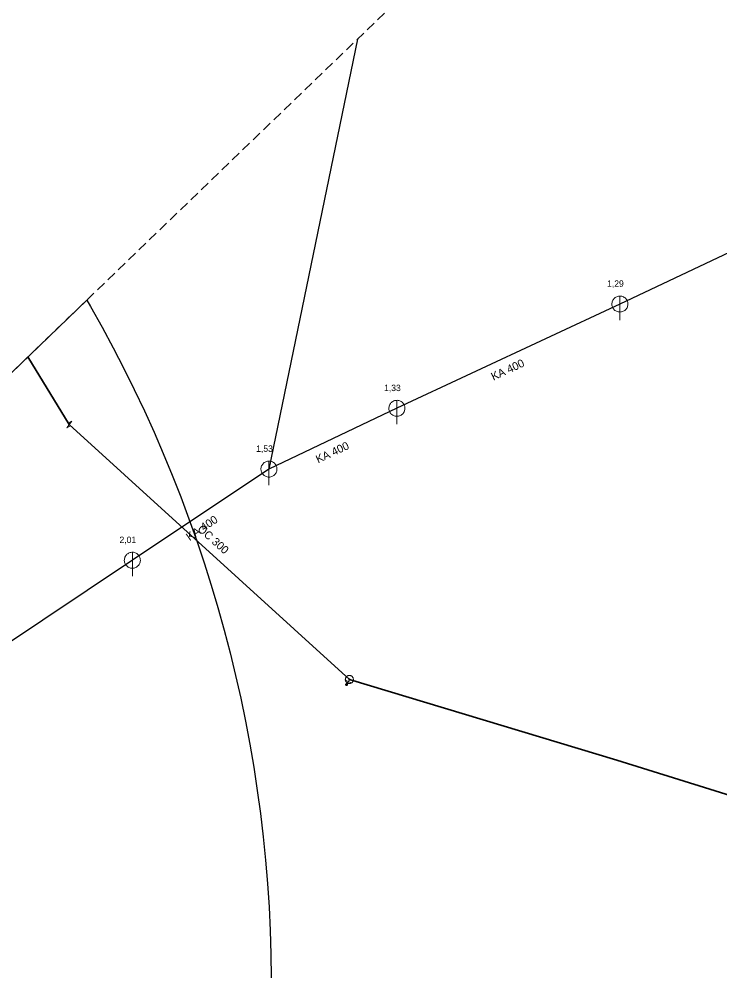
# Model space of a CAD drawing. Extents: x -724334 to -723692, y -972150 to -970648.
# Drawn here: x -724261.9 to -724174.5, y -971124 to -971004.7 of the extents above; entities that cross this region are included whole.
import ezdxf

# ---------------------------------------------------------------- set-up
doc = ezdxf.new("R2010")
doc.units = 0
doc.header["$LTSCALE"] = 0.4
doc.linetypes.add('MEDIUM_DASHED', pattern=[4.5, 3, -1.5])
for name, color, linetype, lineweight in [('1', 7, 'Continuous', 25), ('14', 7, 'Continuous', 25), ('17', 7, 'Continuous', 35), ('22', 7, 'Continuous', 13), ('34', 7, 'Continuous', 13), ('47', 7, 'Continuous', 13), ('9', 7, 'Continuous', 13)]:
    doc.layers.add(name, color=color, linetype=linetype, lineweight=lineweight)

msp = doc.modelspace()

# ---------------------------------------------------------------- linework, layer by layer
at = {"layer": '1', "linetype": 'MEDIUM_DASHED'}
msp.add_lwpolyline([(-723848.074, -970648.428), (-723714.095, -970720.999), (-724065.788, -971064.318), (-723792.249, -971201.088), (-723702.93, -971508.122), (-723691.766, -972150.101), (-723842.491, -972097.068), (-723864.821, -971424.385), (-723982.052, -971259.703), (-724333.745, -971117.352)], close=True, dxfattribs=at)
at = {"layer": '1'}
msp.add_lwpolyline([(-724333.745, -971117.352), (-724253.495, -971039.869), (-724253.028, -971040.67), (-724251.593, -971043.229), (-724250.203, -971045.81), (-724248.858, -971048.413), (-724247.56, -971051.036), (-724246.307, -971053.68), (-724245.1, -971056.344), (-724243.94, -971059.026), (-724242.826, -971061.727), (-724241.758, -971064.446), (-724240.738, -971067.182), (-724239.764, -971069.934), (-724238.838, -971072.703), (-724237.959, -971075.486), (-724237.128, -971078.284), (-724236.345, -971081.096), (-724235.609, -971083.922), (-724234.922, -971086.76), (-724234.283, -971089.61), (-724233.693, -971092.471), (-724233.152, -971095.343), (-724232.659, -971098.226), (-724232.216, -971101.118), (-724231.822, -971104.019), (-724231.478, -971106.928), (-724231.183, -971109.844), (-724230.939, -971112.768), (-724230.744, -971115.698), (-724230.6, -971118.634), (-724230.507, -971121.575), (-724230.464, -971124.52)], dxfattribs=at)
at = {"layer": '14'}
for p, q in [((-724219.714, -971007.253), (-724230.75, -971060.969)), ((-724147.899, -971021.91), (-724186.94, -971040.35)), ((-724186.94, -971040.35), (-724214.78, -971053.379)), ((-724214.78, -971053.379), (-724230.75, -971060.969)), ((-724230.75, -971060.969), (-724247.809, -971072.359)), ((-724247.809, -971072.359), (-724292.363, -971102.175))]:
    msp.add_line(p, q, dxfattribs=at)
at = {"layer": '14', "lineweight": 13}
for p, q in [((-724220.842, -971087.519), (-724221.059, -971087.89)), ((-724220.714, -971087.254), (-724220.842, -971087.519))]:
    msp.add_line(p, q, dxfattribs=at)
at = {"layer": '17'}
for p, q in [((-724255.679, -971055.409), (-724260.846, -971046.966)), ((-724220.714, -971087.254), (-724255.679, -971055.409))]:
    msp.add_line(p, q, dxfattribs=at)
msp.add_lwpolyline([(-723856.75, -971277.52), (-723871.469, -971261.379), (-723894.09, -971234.91), (-723915.739, -971210.25), (-723934.449, -971190.379), (-723958.59, -971177.719), (-723983.8, -971165.17), (-724007.629, -971153.55), (-724038.03, -971139.35), (-724069.469, -971127.41), (-724098.62, -971120.079), (-724100.07, -971119.51), (-724120.89, -971115.66), (-724149.294, -971109.225), (-724187.32, -971097.32), (-724220.714, -971087.254)], dxfattribs=at)
at = {"layer": '22'}
for p, q in [((-724186.94, -971042.35), (-724186.939, -971039.35)), ((-724214.78, -971055.379), (-724214.779, -971052.379)), ((-724230.75, -971062.969), (-724230.749, -971059.969)), ((-724247.809, -971074.359), (-724247.808, -971071.359))]:
    msp.add_line(p, q, dxfattribs=at)
for points in [[(-724185.94, -971040.35), (-724185.945, -971040.241), (-724185.963, -971040.133), (-724185.993, -971040.027), (-724186.033, -971039.926), (-724186.085, -971039.829), (-724186.147, -971039.739), (-724186.219, -971039.656), (-724186.299, -971039.582), (-724186.387, -971039.516), (-724186.481, -971039.461), (-724186.581, -971039.416), (-724186.686, -971039.383), (-724186.793, -971039.361), (-724186.902, -971039.351), (-724187.012, -971039.353), (-724187.12, -971039.367), (-724187.227, -971039.392), (-724187.33, -971039.429), (-724187.428, -971039.478), (-724187.52, -971039.536), (-724187.606, -971039.605), (-724187.683, -971039.682), (-724187.752, -971039.768), (-724187.811, -971039.86), (-724187.859, -971039.958), (-724187.896, -971040.061), (-724187.922, -971040.168), (-724187.936, -971040.276), (-724187.939, -971040.386), (-724187.929, -971040.495), (-724187.908, -971040.602), (-724187.874, -971040.706), (-724187.83, -971040.806), (-724187.775, -971040.901), (-724187.709, -971040.989), (-724187.635, -971041.069), (-724187.552, -971041.141), (-724187.462, -971041.203), (-724187.366, -971041.255), (-724187.264, -971041.296), (-724187.159, -971041.326), (-724187.051, -971041.344), (-724186.941, -971041.35), (-724186.832, -971041.344), (-724186.724, -971041.326), (-724186.619, -971041.297), (-724186.517, -971041.256), (-724186.42, -971041.204), (-724186.33, -971041.142), (-724186.247, -971041.071), (-724186.172, -971040.991), (-724186.107, -971040.903), (-724186.051, -971040.809), (-724186.007, -971040.709), (-724185.973, -971040.605), (-724185.951, -971040.497), (-724185.941, -971040.388)], [(-724213.78, -971053.379), (-724213.785, -971053.27), (-724213.803, -971053.162), (-724213.833, -971053.056), (-724213.873, -971052.955), (-724213.925, -971052.858), (-724213.987, -971052.768), (-724214.059, -971052.685), (-724214.139, -971052.611), (-724214.227, -971052.545), (-724214.321, -971052.49), (-724214.421, -971052.445), (-724214.526, -971052.412), (-724214.633, -971052.39), (-724214.742, -971052.38), (-724214.852, -971052.382), (-724214.96, -971052.396), (-724215.067, -971052.421), (-724215.17, -971052.458), (-724215.268, -971052.507), (-724215.36, -971052.565), (-724215.446, -971052.634), (-724215.523, -971052.711), (-724215.592, -971052.797), (-724215.651, -971052.889), (-724215.699, -971052.987), (-724215.736, -971053.09), (-724215.762, -971053.197), (-724215.776, -971053.305), (-724215.779, -971053.415), (-724215.769, -971053.524), (-724215.748, -971053.631), (-724215.714, -971053.735), (-724215.67, -971053.835), (-724215.615, -971053.93), (-724215.549, -971054.018), (-724215.475, -971054.098), (-724215.392, -971054.17), (-724215.302, -971054.232), (-724215.206, -971054.284), (-724215.104, -971054.325), (-724214.999, -971054.355), (-724214.891, -971054.373), (-724214.781, -971054.379), (-724214.672, -971054.373), (-724214.564, -971054.355), (-724214.459, -971054.326), (-724214.357, -971054.285), (-724214.26, -971054.233), (-724214.17, -971054.171), (-724214.087, -971054.1), (-724214.012, -971054.02), (-724213.947, -971053.932), (-724213.891, -971053.838), (-724213.847, -971053.738), (-724213.813, -971053.634), (-724213.791, -971053.526), (-724213.781, -971053.417)], [(-724229.75, -971060.969), (-724229.755, -971060.86), (-724229.773, -971060.752), (-724229.803, -971060.646), (-724229.843, -971060.545), (-724229.895, -971060.448), (-724229.957, -971060.358), (-724230.029, -971060.275), (-724230.109, -971060.201), (-724230.197, -971060.135), (-724230.291, -971060.08), (-724230.391, -971060.035), (-724230.496, -971060.002), (-724230.603, -971059.98), (-724230.712, -971059.97), (-724230.822, -971059.972), (-724230.93, -971059.986), (-724231.037, -971060.011), (-724231.14, -971060.048), (-724231.238, -971060.097), (-724231.33, -971060.155), (-724231.416, -971060.224), (-724231.493, -971060.301), (-724231.562, -971060.387), (-724231.621, -971060.479), (-724231.669, -971060.577), (-724231.706, -971060.68), (-724231.732, -971060.787), (-724231.746, -971060.895), (-724231.749, -971061.005), (-724231.739, -971061.114), (-724231.718, -971061.221), (-724231.684, -971061.325), (-724231.64, -971061.425), (-724231.585, -971061.52), (-724231.519, -971061.608), (-724231.445, -971061.688), (-724231.362, -971061.76), (-724231.272, -971061.822), (-724231.176, -971061.874), (-724231.074, -971061.915), (-724230.969, -971061.945), (-724230.861, -971061.963), (-724230.751, -971061.969), (-724230.642, -971061.963), (-724230.534, -971061.945), (-724230.429, -971061.916), (-724230.327, -971061.875), (-724230.23, -971061.823), (-724230.14, -971061.761), (-724230.057, -971061.69), (-724229.982, -971061.61), (-724229.917, -971061.522), (-724229.861, -971061.428), (-724229.817, -971061.328), (-724229.783, -971061.224), (-724229.761, -971061.116), (-724229.751, -971061.007)], [(-724246.809, -971072.359), (-724246.814, -971072.25), (-724246.832, -971072.142), (-724246.862, -971072.036), (-724246.902, -971071.935), (-724246.954, -971071.838), (-724247.016, -971071.748), (-724247.088, -971071.665), (-724247.168, -971071.591), (-724247.256, -971071.525), (-724247.35, -971071.47), (-724247.45, -971071.425), (-724247.555, -971071.392), (-724247.662, -971071.37), (-724247.771, -971071.36), (-724247.881, -971071.362), (-724247.989, -971071.376), (-724248.096, -971071.401), (-724248.199, -971071.438), (-724248.297, -971071.487), (-724248.389, -971071.545), (-724248.475, -971071.614), (-724248.552, -971071.691), (-724248.621, -971071.777), (-724248.68, -971071.869), (-724248.728, -971071.967), (-724248.765, -971072.07), (-724248.791, -971072.177), (-724248.805, -971072.285), (-724248.808, -971072.395), (-724248.798, -971072.504), (-724248.777, -971072.611), (-724248.743, -971072.715), (-724248.699, -971072.815), (-724248.644, -971072.91), (-724248.578, -971072.998), (-724248.504, -971073.078), (-724248.421, -971073.15), (-724248.331, -971073.212), (-724248.235, -971073.264), (-724248.133, -971073.305), (-724248.028, -971073.335), (-724247.92, -971073.353), (-724247.81, -971073.359), (-724247.701, -971073.353), (-724247.593, -971073.335), (-724247.488, -971073.306), (-724247.386, -971073.265), (-724247.289, -971073.213), (-724247.199, -971073.151), (-724247.116, -971073.08), (-724247.041, -971073), (-724246.976, -971072.912), (-724246.92, -971072.818), (-724246.876, -971072.718), (-724246.842, -971072.614), (-724246.82, -971072.506), (-724246.81, -971072.397)]]:
    msp.add_lwpolyline(points, close=True, dxfattribs=at)
at = {"layer": '34'}
msp.add_line((-724221.292, -971087.301), (-724220.392, -971087.737), dxfattribs=at)
at = {"layer": '47'}
msp.add_line((-724255.369, -971055.004), (-724255.812, -971055.258), dxfattribs=at)
msp.add_lwpolyline([(-724255.369, -971055.004), (-724255.988, -971055.813), (-724255.545, -971055.559)], dxfattribs=at)
for points in [[(-724220.214, -971087.254), (-724220.217, -971087.201), (-724220.225, -971087.149), (-724220.239, -971087.1), (-724220.257, -971087.051), (-724220.281, -971087.004), (-724220.31, -971086.96), (-724220.343, -971086.919), (-724220.38, -971086.882), (-724220.42, -971086.85), (-724220.464, -971086.821), (-724220.511, -971086.796), (-724220.56, -971086.779), (-724220.61, -971086.765), (-724220.662, -971086.757), (-724220.714, -971086.754), (-724220.766, -971086.757), (-724220.818, -971086.765), (-724220.869, -971086.779), (-724220.917, -971086.796), (-724220.964, -971086.821), (-724221.008, -971086.85), (-724221.049, -971086.882), (-724221.086, -971086.919), (-724221.119, -971086.96), (-724221.147, -971087.004), (-724221.171, -971087.051), (-724221.19, -971087.1), (-724221.203, -971087.149), (-724221.211, -971087.201), (-724221.214, -971087.254), (-724221.211, -971087.306), (-724221.203, -971087.358), (-724221.19, -971087.409), (-724221.171, -971087.456), (-724221.147, -971087.504), (-724221.119, -971087.548), (-724221.086, -971087.588), (-724221.049, -971087.625), (-724221.008, -971087.659), (-724220.964, -971087.686), (-724220.917, -971087.711), (-724220.869, -971087.73), (-724220.818, -971087.742), (-724220.766, -971087.75), (-724220.714, -971087.754), (-724220.662, -971087.75), (-724220.61, -971087.742), (-724220.56, -971087.73), (-724220.511, -971087.711), (-724220.464, -971087.686), (-724220.42, -971087.659), (-724220.38, -971087.625), (-724220.343, -971087.588), (-724220.31, -971087.548), (-724220.281, -971087.504), (-724220.257, -971087.456), (-724220.239, -971087.409), (-724220.225, -971087.358), (-724220.217, -971087.306)], [(-724220.632, -971087.254), (-724220.632, -971087.245), (-724220.634, -971087.237), (-724220.636, -971087.228), (-724220.639, -971087.22), (-724220.643, -971087.213), (-724220.648, -971087.206), (-724220.653, -971087.198), (-724220.659, -971087.193), (-724220.666, -971087.188), (-724220.673, -971087.183), (-724220.681, -971087.179), (-724220.689, -971087.176), (-724220.697, -971087.174), (-724220.705, -971087.171), (-724220.714, -971087.171), (-724220.723, -971087.171), (-724220.731, -971087.174), (-724220.739, -971087.176), (-724220.747, -971087.179), (-724220.755, -971087.183), (-724220.762, -971087.188), (-724220.769, -971087.193), (-724220.775, -971087.198), (-724220.781, -971087.206), (-724220.785, -971087.213), (-724220.789, -971087.22), (-724220.792, -971087.228), (-724220.794, -971087.237), (-724220.796, -971087.245), (-724220.796, -971087.254), (-724220.796, -971087.262), (-724220.794, -971087.271), (-724220.792, -971087.279), (-724220.789, -971087.287), (-724220.785, -971087.294), (-724220.781, -971087.301), (-724220.775, -971087.309), (-724220.769, -971087.315), (-724220.762, -971087.321), (-724220.755, -971087.325), (-724220.747, -971087.328), (-724220.739, -971087.331), (-724220.731, -971087.333), (-724220.723, -971087.336), (-724220.714, -971087.336), (-724220.705, -971087.336), (-724220.697, -971087.333), (-724220.689, -971087.331), (-724220.681, -971087.328), (-724220.673, -971087.325), (-724220.666, -971087.321), (-724220.659, -971087.315), (-724220.653, -971087.309), (-724220.648, -971087.301), (-724220.643, -971087.294), (-724220.639, -971087.287), (-724220.636, -971087.279), (-724220.634, -971087.271), (-724220.632, -971087.262)]]:
    msp.add_lwpolyline(points, close=True, dxfattribs=at)
at = {"layer": '9'}
for points in [[(-724221.185, -971087.89), (-724221.185, -971087.903), (-724221.183, -971087.916), (-724221.18, -971087.929), (-724221.175, -971087.941), (-724221.169, -971087.953), (-724221.162, -971087.964), (-724221.154, -971087.974), (-724221.144, -971087.984), (-724221.134, -971087.992), (-724221.123, -971087.999), (-724221.111, -971088.005), (-724221.099, -971088.01), (-724221.086, -971088.013), (-724221.073, -971088.015), (-724221.06, -971088.017), (-724221.047, -971088.016), (-724221.034, -971088.014), (-724221.021, -971088.011), (-724221.009, -971088.006), (-724220.997, -971088), (-724220.986, -971087.993), (-724220.976, -971087.985), (-724220.966, -971087.975), (-724220.958, -971087.965), (-724220.951, -971087.954), (-724220.945, -971087.942), (-724220.94, -971087.93), (-724220.937, -971087.917), (-724220.935, -971087.904), (-724220.933, -971087.891), (-724220.934, -971087.878), (-724220.936, -971087.865), (-724220.939, -971087.852), (-724220.944, -971087.84), (-724220.95, -971087.828), (-724220.957, -971087.817), (-724220.965, -971087.807), (-724220.975, -971087.797), (-724220.985, -971087.789), (-724220.996, -971087.782), (-724221.008, -971087.776), (-724221.02, -971087.771), (-724221.033, -971087.768), (-724221.046, -971087.766), (-724221.059, -971087.765), (-724221.072, -971087.765), (-724221.085, -971087.767), (-724221.098, -971087.77), (-724221.11, -971087.775), (-724221.122, -971087.781), (-724221.133, -971087.788), (-724221.143, -971087.796), (-724221.153, -971087.806), (-724221.161, -971087.816), (-724221.168, -971087.827), (-724221.174, -971087.839), (-724221.179, -971087.851), (-724221.182, -971087.864), (-724221.184, -971087.877)], [(-724221.165, -971087.89), (-724221.166, -971087.901), (-724221.164, -971087.912), (-724221.161, -971087.923), (-724221.157, -971087.933), (-724221.152, -971087.943), (-724221.146, -971087.952), (-724221.139, -971087.961), (-724221.131, -971087.969), (-724221.122, -971087.976), (-724221.113, -971087.982), (-724221.103, -971087.987), (-724221.093, -971087.991), (-724221.082, -971087.994), (-724221.071, -971087.997), (-724221.06, -971087.997), (-724221.049, -971087.997), (-724221.038, -971087.995), (-724221.027, -971087.992), (-724221.017, -971087.988), (-724221.007, -971087.983), (-724220.998, -971087.977), (-724220.989, -971087.97), (-724220.981, -971087.962), (-724220.974, -971087.953), (-724220.968, -971087.944), (-724220.963, -971087.934), (-724220.959, -971087.924), (-724220.956, -971087.913), (-724220.954, -971087.902), (-724220.953, -971087.891), (-724220.953, -971087.88), (-724220.955, -971087.869), (-724220.958, -971087.858), (-724220.962, -971087.848), (-724220.967, -971087.838), (-724220.973, -971087.829), (-724220.98, -971087.82), (-724220.988, -971087.812), (-724220.997, -971087.805), (-724221.006, -971087.799), (-724221.016, -971087.794), (-724221.026, -971087.79), (-724221.037, -971087.787), (-724221.048, -971087.785), (-724221.059, -971087.785), (-724221.07, -971087.784), (-724221.081, -971087.786), (-724221.092, -971087.789), (-724221.102, -971087.793), (-724221.112, -971087.798), (-724221.121, -971087.804), (-724221.13, -971087.811), (-724221.138, -971087.819), (-724221.145, -971087.828), (-724221.151, -971087.837), (-724221.156, -971087.847), (-724221.16, -971087.857), (-724221.163, -971087.868), (-724221.165, -971087.879)], [(-724221.146, -971087.89), (-724221.146, -971087.899), (-724221.145, -971087.908), (-724221.142, -971087.917), (-724221.139, -971087.925), (-724221.135, -971087.933), (-724221.13, -971087.941), (-724221.124, -971087.948), (-724221.118, -971087.954), (-724221.111, -971087.96), (-724221.103, -971087.965), (-724221.095, -971087.969), (-724221.087, -971087.972), (-724221.078, -971087.975), (-724221.069, -971087.976), (-724221.06, -971087.978), (-724221.051, -971087.977), (-724221.042, -971087.976), (-724221.033, -971087.973), (-724221.025, -971087.97), (-724221.017, -971087.966), (-724221.009, -971087.961), (-724221.002, -971087.955), (-724220.996, -971087.949), (-724220.99, -971087.942), (-724220.985, -971087.934), (-724220.981, -971087.926), (-724220.978, -971087.918), (-724220.975, -971087.909), (-724220.974, -971087.9), (-724220.972, -971087.891), (-724220.973, -971087.882), (-724220.974, -971087.873), (-724220.977, -971087.864), (-724220.98, -971087.856), (-724220.984, -971087.848), (-724220.989, -971087.84), (-724220.995, -971087.833), (-724221.001, -971087.827), (-724221.008, -971087.821), (-724221.016, -971087.816), (-724221.024, -971087.812), (-724221.032, -971087.809), (-724221.041, -971087.806), (-724221.05, -971087.805), (-724221.059, -971087.804), (-724221.068, -971087.804), (-724221.077, -971087.805), (-724221.086, -971087.808), (-724221.094, -971087.811), (-724221.102, -971087.815), (-724221.11, -971087.82), (-724221.117, -971087.826), (-724221.123, -971087.832), (-724221.129, -971087.839), (-724221.134, -971087.847), (-724221.138, -971087.855), (-724221.141, -971087.863), (-724221.144, -971087.872), (-724221.145, -971087.881)], [(-724221.126, -971087.89), (-724221.126, -971087.897), (-724221.125, -971087.904), (-724221.124, -971087.911), (-724221.121, -971087.917), (-724221.118, -971087.923), (-724221.114, -971087.929), (-724221.11, -971087.935), (-724221.105, -971087.94), (-724221.099, -971087.944), (-724221.093, -971087.948), (-724221.087, -971087.951), (-724221.081, -971087.954), (-724221.074, -971087.955), (-724221.067, -971087.958), (-724221.06, -971087.958), (-724221.053, -971087.958), (-724221.046, -971087.956), (-724221.039, -971087.955), (-724221.033, -971087.952), (-724221.026, -971087.949), (-724221.021, -971087.945), (-724221.015, -971087.941), (-724221.01, -971087.936), (-724221.006, -971087.93), (-724221.002, -971087.924), (-724220.999, -971087.918), (-724220.996, -971087.912), (-724220.994, -971087.905), (-724220.993, -971087.898), (-724220.992, -971087.891), (-724220.992, -971087.884), (-724220.993, -971087.877), (-724220.995, -971087.87), (-724220.998, -971087.864), (-724221.001, -971087.857), (-724221.005, -971087.852), (-724221.009, -971087.846), (-724221.014, -971087.841), (-724221.02, -971087.837), (-724221.025, -971087.833), (-724221.032, -971087.83), (-724221.038, -971087.827), (-724221.045, -971087.825), (-724221.052, -971087.824), (-724221.059, -971087.824), (-724221.066, -971087.824), (-724221.073, -971087.824), (-724221.08, -971087.826), (-724221.086, -971087.829), (-724221.092, -971087.832), (-724221.098, -971087.836), (-724221.104, -971087.84), (-724221.109, -971087.845), (-724221.113, -971087.851), (-724221.117, -971087.856), (-724221.12, -971087.863), (-724221.123, -971087.869), (-724221.124, -971087.876), (-724221.126, -971087.883)], [(-724221.106, -971087.89), (-724221.106, -971087.895), (-724221.106, -971087.9), (-724221.105, -971087.905), (-724221.103, -971087.909), (-724221.101, -971087.914), (-724221.098, -971087.918), (-724221.095, -971087.921), (-724221.091, -971087.925), (-724221.088, -971087.928), (-724221.084, -971087.931), (-724221.079, -971087.933), (-724221.075, -971087.935), (-724221.07, -971087.936), (-724221.065, -971087.938), (-724221.06, -971087.938), (-724221.055, -971087.938), (-724221.05, -971087.937), (-724221.045, -971087.936), (-724221.041, -971087.934), (-724221.036, -971087.932), (-724221.032, -971087.929), (-724221.028, -971087.926), (-724221.025, -971087.922), (-724221.022, -971087.919), (-724221.019, -971087.915), (-724221.017, -971087.91), (-724221.015, -971087.906), (-724221.014, -971087.901), (-724221.013, -971087.896), (-724221.012, -971087.891), (-724221.012, -971087.886), (-724221.013, -971087.881), (-724221.014, -971087.876), (-724221.016, -971087.872), (-724221.018, -971087.867), (-724221.021, -971087.863), (-724221.024, -971087.859), (-724221.027, -971087.856), (-724221.031, -971087.853), (-724221.035, -971087.85), (-724221.04, -971087.848), (-724221.044, -971087.846), (-724221.049, -971087.845), (-724221.054, -971087.844), (-724221.059, -971087.844), (-724221.064, -971087.844), (-724221.069, -971087.845), (-724221.074, -971087.845), (-724221.078, -971087.847), (-724221.083, -971087.849), (-724221.087, -971087.852), (-724221.09, -971087.855), (-724221.094, -971087.858), (-724221.097, -971087.862), (-724221.1, -971087.866), (-724221.102, -971087.871), (-724221.104, -971087.875), (-724221.105, -971087.88), (-724221.106, -971087.885)], [(-724221.086, -971087.89), (-724221.086, -971087.893), (-724221.087, -971087.896), (-724221.086, -971087.898), (-724221.085, -971087.901), (-724221.084, -971087.904), (-724221.082, -971087.906), (-724221.08, -971087.908), (-724221.078, -971087.91), (-724221.076, -971087.912), (-724221.074, -971087.914), (-724221.071, -971087.916), (-724221.068, -971087.917), (-724221.066, -971087.917), (-724221.063, -971087.918), (-724221.06, -971087.918), (-724221.057, -971087.918), (-724221.054, -971087.918), (-724221.051, -971087.917), (-724221.049, -971087.916), (-724221.046, -971087.915), (-724221.044, -971087.913), (-724221.041, -971087.911), (-724221.039, -971087.909), (-724221.038, -971087.907), (-724221.036, -971087.905), (-724221.035, -971087.902), (-724221.033, -971087.899), (-724221.033, -971087.897), (-724221.032, -971087.894), (-724221.031, -971087.891), (-724221.032, -971087.888), (-724221.032, -971087.885), (-724221.033, -971087.882), (-724221.034, -971087.88), (-724221.035, -971087.877), (-724221.037, -971087.875), (-724221.038, -971087.872), (-724221.04, -971087.87), (-724221.043, -971087.869), (-724221.045, -971087.867), (-724221.048, -971087.866), (-724221.05, -971087.865), (-724221.053, -971087.864), (-724221.056, -971087.864), (-724221.059, -971087.863), (-724221.062, -971087.864), (-724221.065, -971087.863), (-724221.067, -971087.865), (-724221.07, -971087.865), (-724221.073, -971087.866), (-724221.075, -971087.868), (-724221.077, -971087.869), (-724221.079, -971087.871), (-724221.081, -971087.874), (-724221.083, -971087.876), (-724221.084, -971087.879), (-724221.085, -971087.881), (-724221.086, -971087.884), (-724221.086, -971087.887)], [(-724221.067, -971087.89), (-724221.067, -971087.892), (-724221.067, -971087.892), (-724221.066, -971087.892), (-724221.066, -971087.894), (-724221.067, -971087.895), (-724221.065, -971087.895), (-724221.065, -971087.895), (-724221.065, -971087.897), (-724221.065, -971087.897), (-724221.064, -971087.898), (-724221.062, -971087.898), (-724221.062, -971087.898), (-724221.062, -971087.899), (-724221.06, -971087.899), (-724221.06, -971087.899), (-724221.059, -971087.899), (-724221.058, -971087.899), (-724221.058, -971087.898), (-724221.057, -971087.898), (-724221.055, -971087.898), (-724221.055, -971087.897), (-724221.055, -971087.897), (-724221.054, -971087.896), (-724221.054, -971087.896), (-724221.052, -971087.895), (-724221.052, -971087.894), (-724221.051, -971087.893), (-724221.051, -971087.893), (-724221.051, -971087.892), (-724221.051, -971087.891), (-724221.051, -971087.89), (-724221.051, -971087.889), (-724221.051, -971087.889), (-724221.052, -971087.888), (-724221.052, -971087.887), (-724221.053, -971087.886), (-724221.053, -971087.886), (-724221.054, -971087.885), (-724221.054, -971087.885), (-724221.055, -971087.884), (-724221.056, -971087.884), (-724221.057, -971087.883), (-724221.057, -971087.883), (-724221.058, -971087.883), (-724221.059, -971087.883), (-724221.06, -971087.883), (-724221.061, -971087.883), (-724221.061, -971087.883), (-724221.062, -971087.884), (-724221.063, -971087.883), (-724221.064, -971087.885), (-724221.064, -971087.885), (-724221.065, -971087.885), (-724221.065, -971087.885), (-724221.066, -971087.887), (-724221.066, -971087.888), (-724221.066, -971087.889), (-724221.067, -971087.889), (-724221.067, -971087.89)]]:
    msp.add_lwpolyline(points, close=True, dxfattribs=at)

# ---------------------------------------------------------------- texts
at = {"layer": '1'}
for s, p in [('1,29', (-724188.539, -971038.197)), ('1,33', (-724216.38, -971051.227)), ('1,53', (-724232.349, -971058.817)), ('2,01', (-724249.41, -971070.207))]:
    msp.add_text(s, height=0.8, dxfattribs=at).set_placement(p)
for s, rotation, p in [('KA 400', 25, (-724202.735, -971049.934)), ('KA 400', 25, (-724224.621, -971060.255)), ('KA 400', 34, (-724240.672, -971069.981)), ('OC 300', 318, (-724239.75, -971068.582))]:
    msp.add_text(s, height=1, rotation=rotation, dxfattribs=at).set_placement(p)

doc.saveas('drawing.dxf')
